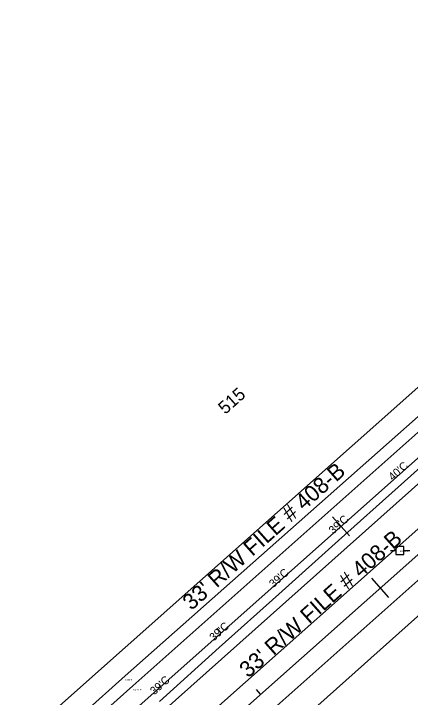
# Model space of a CAD drawing. Extents: x 50001 to 56005, y 49075 to 53926.
# Drawn here: x 53088.1 to 53335.6, y 51241.1 to 51667.9 of the extents above; entities that cross this region are included whole.
import ezdxf

# ---------------------------------------------------------------- set-up
doc = ezdxf.new("R2010")
doc.units = 0
for name, color, linetype in [('Level 1', 7, 'Continuous'), ('Level 11', 7, 'Continuous'), ('Level 12', 7, 'Continuous'), ('Level 18', 7, 'Continuous'), ('Level 19', 7, 'Continuous'), ('Level 20', 7, 'Continuous'), ('Level 21', 7, 'Continuous'), ('Level 25', 7, 'Continuous'), ('Level 3', 7, 'Continuous'), ('Level 53', 7, 'Continuous'), ('Level 59', 7, 'Continuous'), ('Level 61', 7, 'Continuous'), ('Level 9', 7, 'Continuous')]:
    doc.layers.add(name, color=color, linetype=linetype)

# ---------------------------------------------------------------- blocks, each defined once
blk = doc.blocks.new('PP')
at = {"layer": 'Level 9'}
for p, q in [((2.53, 2.45), (-2.47, 2.45)), ((-2.47, 2.45), (-2.47, -2.55)), ((2.53, -2.55), (2.53, 2.45)), ((-5.91, -0.11), (-2.44, -0.11)), ((-2.47, -2.55), (2.53, -2.55)), ((2.45, -0.11), (6.09, -0.11))]:
    blk.add_line(p, q, dxfattribs=at)

msp = doc.modelspace()

# ---------------------------------------------------------------- linework, layer by layer
at = {"layer": 'Level 1'}
for p, q in [((52544.81, 50683.3), (55534.58, 53340.86)), ((52714.15, 50773.62), (54181.77, 52078.16)), ((53292.35, 51347.78), (53287.03, 51353.76)), ((53292.35, 51347.78), (53297.66, 51341.8)), ((53217.61, 51281.34), (53214.95, 51284.33))]:
    msp.add_line(p, q, dxfattribs=at)
at = {"layer": 'Level 11'}
for p, q in [((53245.86, 51207.55), (53944.24, 51830.77)), ((53157.7, 51254.45), (53424.49, 51490.93)), ((52940.3, 51059.99), (53157.7, 51254.45))]:
    msp.add_line(p, q, dxfattribs=at)
at = {"layer": 'Level 12'}
for p, q in [((52637.37, 50809.73), (53363.85, 51455.49)), ((53407.7, 51406.16), (52566.74, 50658.64))]:
    msp.add_line(p, q, dxfattribs=at)
at = {"layer": 'Level 18'}
for p, q in [((53327.91, 51372.27), (53365.15, 51405.63)), ((53290.69, 51338.88), (53327.91, 51372.27)), ((53253.46, 51305.5), (53290.69, 51338.88)), ((53216.24, 51272.11), (53253.46, 51305.5)), ((53179.19, 51238.54), (53216.24, 51272.11))]:
    msp.add_line(p, q, dxfattribs=at)
at = {"layer": 'Level 19'}
for p, q in [((52714.15, 50773.62), (54181.77, 52078.16)), ((53322.21, 51303.41), (53311.58, 51315.37)), ((53242.16, 51242.96), (53239.5, 51245.95))]:
    msp.add_line(p, q, dxfattribs=at)
at = {"layer": 'Level 20'}
for p, q in [((52706.17, 50782.58), (53452.43, 51445.92)), ((52722.12, 50764.65), (53468.37, 51427.98))]:
    msp.add_line(p, q, dxfattribs=at)
at = {"layer": 'Level 3'}
for p, q in [((53162.5, 51248.32), (53434.09, 51489.84)), ((53179.35, 51230.72), (53449.72, 51471.81)), ((52945.93, 51055.32), (53162.5, 51248.32))]:
    msp.add_line(p, q, dxfattribs=at)

# ---------------------------------------------------------------- block references
at = {"layer": 'Level 9'}
msp.add_blockref('PP', (53329.09, 51332.81), dxfattribs=at)

# ---------------------------------------------------------------- texts
at = {"layer": 'Level 18'}
for s, rotation, p in [("40'C", 41.6333, (53324.58, 51376)), ("39'C", 41.6334, (53287.37, 51342.61)), ("39'C", 41.6334, (53250.14, 51309.24)), ("39'C", 41.6334, (53212.92, 51275.85)), ("39'C", 41.6334, (53175.87, 51242.27))]:
    msp.add_text(s, height=5, rotation=rotation, dxfattribs=at).set_placement(p)
at = {"layer": 'Level 21'}
msp.add_text('515', height=8, rotation=41.6333, dxfattribs=at).set_placement((53220.1, 51417.35))
at = {"layer": 'Level 25'}
for p in [(53199, 51294.91), (53234.4, 51252.78)]:
    msp.add_text("33' R/W FILE # 408-B", height=10, rotation=41.6333, dxfattribs=at).set_placement(p)
at = {"layer": 'Level 53'}
msp.add_text('1331 EPL', height=1, dxfattribs=at).set_placement((53162.5, 51245.32))
at = {"layer": 'Level 59'}
msp.add_text('1336 PP', height=1, dxfattribs=at).set_placement((53329.09, 51331.81))
at = {"layer": 'Level 61'}
msp.add_text('1333 TL', height=1, dxfattribs=at).set_placement((53157.7, 51251.45))

doc.saveas('drawing.dxf')
